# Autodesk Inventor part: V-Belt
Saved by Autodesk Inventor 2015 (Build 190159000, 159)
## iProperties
Created: 2015-03
Part Number: V-Belt
Material: Rubber
Document SubType Name: Modeling
Designer: Uglješa
Density: 0.93 g/cm^3
Appearance: Rubber - Black - Version 1.1
CustomPartVersion: 1
Author: Uglješa
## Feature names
1. Belt
## Parameters: da_Alfa = 40 deg, da_H = 6 mm, da_Bw = 8.5 mm, da_Hw = 2.49859 mm, d0 = 8.5 mm, d1 = 2.49859 mm, d2 = 40 deg, d3 = 6 mm, d4 = 0, d5 = 0, d6 = 0, d7 = 0, d8 = 0, d9 = 0
